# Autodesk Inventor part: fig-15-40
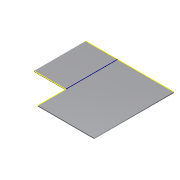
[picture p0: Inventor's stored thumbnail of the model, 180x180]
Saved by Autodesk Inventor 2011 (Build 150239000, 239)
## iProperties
Created: 2005-03
Part Number: fig-15-40
Document SubType Name: Sheet Metal
Designer: CADCIM
Manufacturer: Standard
Standards Organization: Custom
Density: 1 g/cm^3
Sheet Metal Rule: Default
Author: CADCIM
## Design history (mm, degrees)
node "Face1"
  sketch "Sketch1"
    geometry: L1 (31.393, 35.714)-(-19.875, 35.714); L2 (-19.875, 35.714)-(-19.875, 5.625); L3 (-19.875, 5.625)-(-1.5, 5.625); L4 (-1.5, 5.625)-(-1.5, -10.705); L5 (-1.5, -10.705)-(31.393, -10.705); L6 (31.393, -10.705)-(31.393, 35.714)
    constraints: 12 end point, 4 parallel, 1 horizontal, 1 perpendicular
sketch "Sketch3"
  geometry: L1 (18.375, -30.089)-(18.375, 0); L2 (18.375, -46.42)-(18.375, -30.089) reference; L3 (18.375, -30.089)-(0, -30.089) reference; L4 (0, 0)-(51.268, 0) reference
  constraints: 3 point on line, 2 end point, 1 vertical
body "Solid1"
face "Plate1" dims "Thickness" = 0.5
other parameters: "BendRadius" = 0.5 (= Thickness), "BendReliefWidth" = 0.5 (= Thickness), "BendReliefDepth" = 0.25 (= 0.5 x Thickness), "CornerReliefSize" = 2 (= 4 x Thickness), "SeamGap" = 0.01, "MinimumRemnant" = 1 (= 2 x Thickness), "TransitionRadius" = 0.5 (= BendRadius), "d0" = 0.5 (= BendRadius), "JacobiRadiusSize" = 0.5 (= Thickness), "GapSize" = 0.5 (= Thickness)
